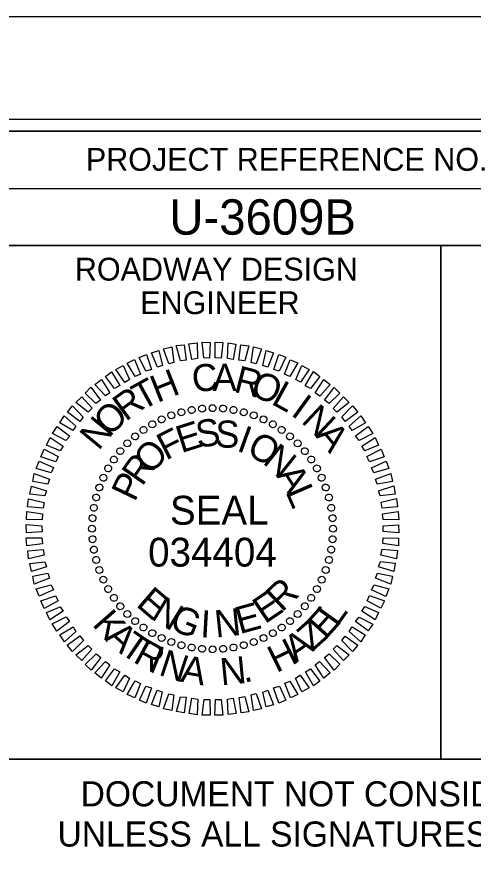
# Model space of a CAD drawing. Extents: x 2331575 to 2333259, y 609001 to 610101.
# Drawn here: x 2333049.3 to 2333149.3, y 609916 to 610101.5 of the extents above; entities that cross this region are included whole.
import ezdxf

# ---------------------------------------------------------------- set-up
doc = ezdxf.new("R2010")
doc.units = 0
for name, color, linetype in [('Sheet Cutting Line CELL', 7, 'Continuous'), ('Sheet Data Field CELL', 7, 'Continuous'), ('Sheet Plan CELL', 7, 'Continuous'), ('Sheet Plot Border Inside CELL', 7, 'Continuous'), ('Sheet Plot Border Outside CELL', 7, 'Continuous'), ('Sheet Profile CELL', 7, 'Continuous'), ('Sheet Profile Grid Major CELL', 7, 'Continuous'), ('Sheet Sticker Exception Certification CELL', 7, 'Continuous')]:
    doc.layers.add(name, color=color, linetype=linetype)

msp = doc.modelspace()

# ---------------------------------------------------------------- linework, layer by layer
at = {"layer": 'Sheet Cutting Line CELL'}
msp.add_line((2333259.23, 610101.48), (2331575.23, 610101.48), dxfattribs=at)
at = {"layer": 'Sheet Data Field CELL'}
for p, q in [((2333089.86, 610015.73), (2333089.86, 610015.73)), ((2333092.18, 610015.83), (2333092.18, 610015.83)), ((2333094.49, 610015.71), (2333094.49, 610015.71)), ((2333083.09, 610014.25), (2333083.09, 610014.25)), ((2333085.29, 610014.92), (2333085.29, 610014.92)), ((2333087.6, 610015.38), (2333087.6, 610015.38)), ((2333096.77, 610015.38), (2333096.77, 610015.38)), ((2333098.99, 610014.95), (2333098.99, 610014.95)), ((2333101.21, 610014.25), (2333101.21, 610014.25)), ((2333078.97, 610012.28), (2333078.97, 610012.28)), ((2333081, 610013.37), (2333081, 610013.37)), ((2333103.33, 610013.34), (2333103.33, 610013.34)), ((2333105.4, 610012.32), (2333105.4, 610012.32)), ((2333076.99, 610011.03), (2333076.99, 610011.03)), ((2333107.32, 610011.04), (2333107.32, 610011.04)), ((2333073.46, 610008.07), (2333073.46, 610008.07)), ((2333075.17, 610009.69), (2333075.17, 610009.69)), ((2333109.19, 610009.65), (2333109.19, 610009.65)), ((2333110.85, 610008.1), (2333110.85, 610008.1)), ((2333071.91, 610006.42), (2333071.91, 610006.42)), ((2333112.46, 610006.39), (2333112.46, 610006.39)), ((2333070.52, 610004.55), (2333070.52, 610004.55)), ((2333113.81, 610004.57), (2333113.81, 610004.57)), ((2333069.23, 610002.63), (2333069.23, 610002.63)), ((2333115.05, 610002.59), (2333115.05, 610002.59)), ((2333068.22, 610000.56), (2333068.22, 610000.56)), ((2333116.14, 610000.55), (2333116.14, 610000.55)), ((2333067.3, 609998.43), (2333067.3, 609998.43)), ((2333117.02, 609998.46), (2333117.02, 609998.46)), ((2333066.61, 609996.21), (2333066.61, 609996.21)), ((2333117.69, 609996.26), (2333117.69, 609996.26)), ((2333066.17, 609993.99), (2333066.17, 609993.99)), ((2333118.15, 609993.95), (2333118.15, 609993.95)), ((2333065.84, 609991.72), (2333065.84, 609991.72)), ((2333118.51, 609991.69), (2333118.51, 609991.69)), ((2333065.72, 609989.4), (2333065.72, 609989.4)), ((2333118.6, 609989.38), (2333118.6, 609989.38)), ((2333065.82, 609987.09), (2333065.82, 609987.09)), ((2333118.49, 609987.06), (2333118.49, 609987.06)), ((2333066.17, 609984.83), (2333066.17, 609984.83)), ((2333118.16, 609984.79), (2333118.16, 609984.79)), ((2333066.63, 609982.52), (2333066.63, 609982.52)), ((2333117.72, 609982.57), (2333117.72, 609982.57)), ((2333067.3, 609980.32), (2333067.3, 609980.32)), ((2333117.02, 609980.34), (2333117.02, 609980.34)), ((2333068.18, 609978.23), (2333068.18, 609978.23)), ((2333116.11, 609978.22), (2333116.11, 609978.22)), ((2333069.27, 609976.19), (2333069.27, 609976.19)), ((2333115.09, 609976.15), (2333115.09, 609976.15)), ((2333070.52, 609974.21), (2333070.52, 609974.21)), ((2333113.81, 609974.23), (2333113.81, 609974.23)), ((2333071.87, 609972.39), (2333071.87, 609972.39)), ((2333112.42, 609972.36), (2333112.42, 609972.36)), ((2333073.48, 609970.68), (2333073.48, 609970.68)), ((2333075.14, 609969.13), (2333075.14, 609969.13)), ((2333110.87, 609970.7), (2333110.87, 609970.7)), ((2333077, 609967.74), (2333077, 609967.74)), ((2333107.34, 609967.74), (2333107.34, 609967.74)), ((2333109.16, 609969.09), (2333109.16, 609969.09)), ((2333078.92, 609966.46), (2333078.92, 609966.46)), ((2333080.99, 609965.44), (2333080.99, 609965.44)), ((2333103.33, 609965.41), (2333103.33, 609965.41)), ((2333105.36, 609966.5), (2333105.36, 609966.5)), ((2333083.12, 609964.53), (2333083.12, 609964.53)), ((2333085.34, 609963.83), (2333085.34, 609963.83)), ((2333099.03, 609963.86), (2333099.03, 609963.86)), ((2333101.23, 609964.53), (2333101.23, 609964.53)), ((2333087.56, 609963.4), (2333087.56, 609963.4)), ((2333089.83, 609963.07), (2333089.83, 609963.07)), ((2333092.15, 609962.95), (2333092.15, 609962.95)), ((2333094.47, 609963.04), (2333094.47, 609963.04)), ((2333096.73, 609963.4), (2333096.73, 609963.4))]:
    msp.add_line(p, q, dxfattribs=at)
for points in [[(2333082.58, 610025.51), (2333081.42, 610028.81), (2333083.2, 610029.21), (2333083.68, 610025.79)], [(2333085.1, 610026.13), (2333084.19, 610029.49), (2333085.93, 610029.68), (2333086.36, 610026.31)], [(2333087.62, 610026.49), (2333086.98, 610029.85), (2333088.77, 610030.09), (2333088.88, 610026.67)], [(2333090.25, 610026.8), (2333089.92, 610030.22), (2333091.66, 610030.2), (2333091.51, 610026.77)], [(2333092.77, 610026.79), (2333092.71, 610030.22), (2333094.45, 610030.19), (2333094.04, 610026.76)], [(2333095.41, 610026.68), (2333095.56, 610030.11), (2333097.3, 610029.82), (2333096.68, 610026.49)], [(2333097.94, 610026.3), (2333098.36, 610029.68), (2333100.1, 610029.45), (2333099.21, 610026.17)], [(2333100.64, 610025.77), (2333101.11, 610029.2), (2333102.9, 610028.81), (2333101.75, 610025.53)], [(2333077.5, 610023.89), (2333076.08, 610026.92), (2333077.65, 610027.58), (2333078.81, 610024.23)], [(2333080.06, 610024.78), (2333078.8, 610027.92), (2333080.42, 610028.42), (2333081.16, 610025.17)], [(2333103.18, 610025.13), (2333103.91, 610028.41), (2333105.55, 610027.91), (2333104.29, 610024.78)], [(2333105.56, 610024.23), (2333106.72, 610027.56), (2333108.2, 610026.96), (2333106.78, 610023.88)], [(2333072.96, 610021.44), (2333070.96, 610024.25), (2333072.58, 610025.12), (2333073.95, 610022.09)], [(2333075.2, 610022.75), (2333073.46, 610025.67), (2333075.08, 610026.43), (2333076.35, 610023.24)], [(2333107.95, 610023.27), (2333109.21, 610026.4), (2333110.86, 610025.69), (2333109.12, 610022.71)], [(2333110.39, 610022.1), (2333111.76, 610025.12), (2333113.36, 610024.26), (2333111.41, 610021.48)], [(2333070.67, 610020.09), (2333068.67, 610022.74), (2333070.02, 610023.76), (2333071.81, 610020.74)], [(2333112.47, 610020.71), (2333114.26, 610023.8), (2333115.65, 610022.72), (2333113.64, 610020.1)], [(2333068.69, 610018.47), (2333066.38, 610020.96), (2333067.79, 610022.09), (2333069.68, 610019.17)], [(2333114.66, 610019.17), (2333116.56, 610022.1), (2333117.95, 610020.97), (2333115.67, 610018.45)], [(2333066.61, 610016.8), (2333064.26, 610019.08), (2333065.5, 610020.37), (2333067.6, 610017.56)], [(2333116.69, 610017.57), (2333118.8, 610020.35), (2333120.08, 610019.11), (2333117.7, 610016.8)], [(2333064.91, 610014.93), (2333062.19, 610017.04), (2333063.48, 610018.28), (2333065.74, 610015.79)], [(2333118.62, 610015.76), (2333120.84, 610018.28), (2333122.12, 610017.04), (2333119.42, 610014.93)], [(2333063.1, 610012.9), (2333060.33, 610014.9), (2333061.46, 610016.29), (2333063.82, 610013.86)], [(2333120.49, 610013.9), (2333122.87, 610016.31), (2333124, 610014.91), (2333121.25, 610012.86)], [(2333061.56, 610010.87), (2333058.68, 610012.61), (2333059.66, 610014.15), (2333062.22, 610011.88)], [(2333122.11, 610011.87), (2333124.65, 610014.13), (2333125.68, 610012.62), (2333122.76, 610010.88)], [(2333123.51, 610009.74), (2333126.27, 610011.79), (2333127.3, 610010.23), (2333124.27, 610008.7)], [(2333060.01, 610008.74), (2333057.04, 610010.26), (2333058.07, 610011.76), (2333060.84, 610009.7)], [(2333058.79, 610006.45), (2333055.77, 610007.71), (2333056.53, 610009.36), (2333059.4, 610007.46)], [(2333124.92, 610007.45), (2333127.84, 610009.34), (2333128.55, 610007.72), (2333125.57, 610006.46)], [(2333057.78, 610004.01), (2333054.49, 610005.16), (2333055.26, 610006.81), (2333058.29, 610005.18)], [(2333126.01, 610005.2), (2333129.09, 610006.83), (2333129.81, 610005.16), (2333126.56, 610004.05)], [(2333056.77, 610001.67), (2333053.49, 610002.56), (2333054.14, 610004.21), (2333057.33, 610002.79)], [(2333127.01, 610002.74), (2333130.19, 610004.17), (2333130.8, 610002.55), (2333127.55, 610001.65)], [(2333056.02, 609999.13), (2333052.74, 609999.76), (2333053.08, 610001.5), (2333056.42, 610000.25)], [(2333127.89, 610000.23), (2333131.24, 610001.5), (2333131.59, 609999.77), (2333128.28, 609999.13)], [(2333055.38, 609996.59), (2333052.11, 609996.96), (2333052.45, 609998.75), (2333055.78, 609997.71)], [(2333128.57, 609997.71), (2333131.87, 609998.77), (2333132.22, 609996.99), (2333128.9, 609996.61)], [(2333055.01, 609993.9), (2333051.63, 609994.16), (2333051.81, 609995.95), (2333055.25, 609995.17)], [(2333129.09, 609995.2), (2333132.5, 609995.99), (2333132.69, 609994.2), (2333129.32, 609993.93)], [(2333054.79, 609991.37), (2333051.36, 609991.41), (2333051.44, 609993.15), (2333054.87, 609992.63)], [(2333129.45, 609992.67), (2333132.86, 609993.15), (2333133, 609991.37), (2333129.57, 609991.41)], [(2333054.78, 609988.74), (2333051.36, 609988.52), (2333051.33, 609990.31), (2333054.76, 609990)], [(2333129.55, 609990.04), (2333132.96, 609990.26), (2333133, 609988.47), (2333129.57, 609988.78)], [(2333054.88, 609986.1), (2333051.46, 609985.62), (2333051.33, 609987.41), (2333054.75, 609987.37)], [(2333129.54, 609987.41), (2333132.96, 609987.36), (2333132.89, 609985.62), (2333129.46, 609986.14)], [(2333055.24, 609983.58), (2333051.83, 609982.79), (2333051.64, 609984.57), (2333055.01, 609984.84)], [(2333129.32, 609984.88), (2333132.7, 609984.62), (2333132.52, 609982.83), (2333129.08, 609983.61)], [(2333055.76, 609981.06), (2333052.46, 609980.01), (2333052.11, 609981.79), (2333055.42, 609982.16)], [(2333128.95, 609982.18), (2333132.22, 609981.82), (2333131.88, 609980.02), (2333128.54, 609981.07)], [(2333056.43, 609978.55), (2333053.09, 609977.28), (2333052.74, 609979.01), (2333056.05, 609979.65)], [(2333128.31, 609979.64), (2333131.58, 609979.02), (2333131.24, 609977.27), (2333127.9, 609978.53)], [(2333057.32, 609976.03), (2333054.13, 609974.61), (2333053.52, 609976.23), (2333056.77, 609977.13)], [(2333127.56, 609977.1), (2333130.84, 609976.21), (2333130.18, 609974.57), (2333127, 609975.99)], [(2333058.31, 609973.58), (2333055.23, 609971.94), (2333054.52, 609973.62), (2333057.76, 609974.73)], [(2333126.55, 609974.77), (2333129.83, 609973.61), (2333129.07, 609971.97), (2333126.04, 609973.6)], [(2333059.4, 609971.33), (2333056.49, 609969.44), (2333055.77, 609971.06), (2333058.75, 609972.32)], [(2333125.54, 609972.33), (2333128.56, 609971.06), (2333127.8, 609969.42), (2333124.92, 609971.32)], [(2333060.81, 609969.04), (2333058.06, 609966.99), (2333057.03, 609968.55), (2333060.06, 609970.08)], [(2333124.31, 609970.04), (2333127.29, 609968.51), (2333126.26, 609967.02), (2333123.49, 609969.08)], [(2333062.22, 609966.9), (2333059.68, 609964.65), (2333058.65, 609966.16), (2333061.57, 609967.89)], [(2333122.77, 609967.91), (2333125.64, 609966.17), (2333124.67, 609964.62), (2333122.1, 609966.9)], [(2333063.84, 609964.88), (2333061.45, 609962.47), (2333060.32, 609963.87), (2333063.08, 609965.92)], [(2333121.22, 609965.88), (2333124, 609963.87), (2333122.86, 609962.49), (2333120.5, 609964.92)], [(2333065.71, 609963.01), (2333063.49, 609960.5), (2333062.2, 609961.74), (2333064.91, 609963.84)], [(2333119.42, 609963.85), (2333122.14, 609961.74), (2333120.84, 609960.5), (2333118.59, 609962.99)], [(2333067.64, 609961.2), (2333065.53, 609958.43), (2333064.24, 609959.67), (2333066.62, 609961.98)], [(2333117.71, 609961.97), (2333120.07, 609959.7), (2333118.83, 609958.41), (2333116.72, 609961.22)], [(2333069.67, 609959.61), (2333067.77, 609956.68), (2333066.38, 609957.81), (2333068.66, 609960.33)], [(2333115.63, 609960.31), (2333117.94, 609957.82), (2333116.54, 609956.69), (2333114.65, 609959.6)], [(2333071.85, 609958.07), (2333070.06, 609954.98), (2333068.68, 609956.06), (2333070.68, 609958.68)], [(2333113.66, 609958.69), (2333115.66, 609956.04), (2333114.3, 609955.02), (2333112.51, 609958.04)], [(2333073.93, 609956.68), (2333072.56, 609953.65), (2333070.97, 609954.52), (2333072.92, 609957.29)], [(2333111.37, 609957.33), (2333113.37, 609954.52), (2333111.75, 609953.65), (2333110.38, 609956.68)], [(2333076.38, 609955.51), (2333075.11, 609952.38), (2333073.47, 609953.09), (2333075.21, 609956.07)], [(2333078.76, 609954.55), (2333077.61, 609951.21), (2333076.12, 609951.82), (2333077.54, 609954.9)], [(2333106.83, 609954.88), (2333108.25, 609951.85), (2333106.68, 609951.2), (2333105.52, 609954.55)], [(2333109.13, 609956.03), (2333110.86, 609953.11), (2333109.24, 609952.35), (2333107.98, 609955.54)], [(2333081.15, 609953.65), (2333080.42, 609950.37), (2333078.77, 609950.87), (2333080.04, 609954)], [(2333083.69, 609953.01), (2333083.22, 609949.57), (2333081.42, 609949.96), (2333082.58, 609953.25)], [(2333086.38, 609952.47), (2333085.97, 609949.1), (2333084.23, 609949.33), (2333085.12, 609952.61)], [(2333099.23, 609952.65), (2333100.13, 609949.29), (2333098.4, 609949.1), (2333097.97, 609952.46)], [(2333101.75, 609953.27), (2333102.91, 609949.97), (2333101.13, 609949.57), (2333100.65, 609952.99)], [(2333104.26, 609954), (2333105.53, 609950.86), (2333103.91, 609950.36), (2333103.16, 609953.61)], [(2333088.92, 609952.1), (2333088.77, 609948.67), (2333087.02, 609948.96), (2333087.65, 609952.29)], [(2333091.55, 609951.98), (2333091.61, 609948.56), (2333089.87, 609948.58), (2333090.29, 609952.01)], [(2333094.08, 609951.98), (2333094.4, 609948.56), (2333092.67, 609948.58), (2333092.82, 609952.01)], [(2333096.71, 609952.29), (2333097.35, 609948.93), (2333095.56, 609948.68), (2333095.45, 609952.1)]]:
    msp.add_lwpolyline(points, close=True, dxfattribs=at)
for centre, major_axis in [((2333085.33, 610014.9), (-0.196, 0.732)), ((2333087.58, 610015.4), (-0.132, 0.747)), ((2333089.86, 610015.7), (-0.066, 0.755)), ((2333092.16, 610015.8), (0, 0.758)), ((2333094.47, 610015.7), (0.066, 0.755)), ((2333096.75, 610015.4), (0.132, 0.747)), ((2333099, 610014.9), (0.196, 0.732)), ((2333081, 610013.33), (-0.32, 0.687)), ((2333083.13, 610014.21), (-0.259, 0.713)), ((2333101.2, 610014.21), (0.259, 0.713)), ((2333103.33, 610013.33), (0.32, 0.687)), ((2333077.01, 610011.03), (-0.435, 0.621)), ((2333078.96, 610012.26), (-0.379, 0.657)), ((2333105.37, 610012.26), (0.379, 0.657)), ((2333107.31, 610011.03), (0.435, 0.621)), ((2333075.18, 610009.62), (-0.487, 0.581)), ((2333109.14, 610009.62), (0.487, 0.581)), ((2333073.49, 610008.07), (-0.536, 0.536)), ((2333110.84, 610008.07), (0.536, 0.536)), ((2333071.93, 610006.37), (-0.581, 0.487)), ((2333112.4, 610006.37), (0.581, 0.487)), ((2333070.53, 610004.54), (-0.621, 0.435)), ((2333113.8, 610004.54), (0.621, 0.435)), ((2333069.29, 610002.6), (-0.657, 0.379)), ((2333115.04, 610002.6), (0.657, 0.379)), ((2333068.22, 610000.55), (-0.687, 0.32)), ((2333116.1, 610000.55), (0.687, 0.32)), ((2333067.34, 609998.42), (-0.713, 0.259)), ((2333116.98, 609998.42), (0.713, 0.259)), ((2333066.65, 609996.22), (-0.732, 0.196)), ((2333117.68, 609996.23), (0.732, 0.196)), ((2333066.15, 609993.98), (-0.747, 0.132)), ((2333118.18, 609993.98), (0.747, 0.132)), ((2333065.85, 609991.69), (-0.755, 0.066)), ((2333118.48, 609991.69), (0.755, 0.066)), ((2333065.75, 609989.39), (-0.758, 0)), ((2333118.58, 609989.39), (0.758, 0)), ((2333065.85, 609987.09), (-0.755, -0.066)), ((2333118.48, 609987.09), (0.755, -0.066)), ((2333066.15, 609984.8), (-0.747, -0.132)), ((2333118.18, 609984.8), (0.747, -0.132)), ((2333066.65, 609982.55), (-0.732, -0.196)), ((2333117.68, 609982.55), (0.732, -0.196)), ((2333067.34, 609980.35), (-0.713, -0.259)), ((2333116.98, 609980.35), (0.713, -0.259)), ((2333068.22, 609978.23), (-0.687, -0.32)), ((2333116.1, 609978.23), (0.687, -0.32)), ((2333069.29, 609976.18), (-0.657, -0.379)), ((2333115.04, 609976.18), (0.657, -0.379)), ((2333070.53, 609974.24), (-0.621, -0.435)), ((2333113.8, 609974.24), (0.621, -0.435)), ((2333071.93, 609972.41), (-0.581, -0.487)), ((2333112.4, 609972.41), (0.581, -0.487)), ((2333073.49, 609970.71), (-0.536, -0.536)), ((2333110.84, 609970.71), (0.536, -0.536)), ((2333075.19, 609969.15), (-0.487, -0.581)), ((2333109.14, 609969.15), (0.487, -0.581)), ((2333077.01, 609967.75), (-0.435, -0.621)), ((2333078.96, 609966.51), (-0.379, -0.657)), ((2333105.37, 609966.51), (0.379, -0.657)), ((2333107.31, 609967.75), (0.435, -0.621)), ((2333081, 609965.45), (-0.32, -0.687)), ((2333083.13, 609964.57), (-0.259, -0.713)), ((2333101.2, 609964.57), (0.259, -0.713)), ((2333103.33, 609965.45), (0.32, -0.687)), ((2333085.33, 609963.87), (-0.196, -0.732)), ((2333087.58, 609963.38), (-0.132, -0.747)), ((2333089.86, 609963.08), (-0.066, -0.755)), ((2333092.16, 609962.97), (0, -0.758)), ((2333094.47, 609963.08), (0.066, -0.755)), ((2333096.75, 609963.38), (0.132, -0.747)), ((2333099, 609963.88), (0.196, -0.732))]:
    msp.add_ellipse(centre, major_axis=major_axis, ratio=0.999708, dxfattribs=at)
at = {"layer": 'Sheet Plot Border Inside CELL'}
msp.add_lwpolyline([(2331588.23, 609023.93), (2333254.73, 609023.93), (2333254.73, 610079.03), (2331588.23, 610079.03)], close=True, dxfattribs=at)
at = {"layer": 'Sheet Plot Border Outside CELL'}
msp.add_lwpolyline([(2331575.23, 609001.48), (2333259.23, 609001.48), (2333259.23, 610101.48), (2331575.23, 610101.48)], close=True, dxfattribs=at)
at = {"layer": 'Sheet Profile CELL'}
for p, q in [((2333042.18, 610063.93), (2333242.23, 610063.93)), ((2333142.23, 610051.43), (2333142.23, 609938.98))]:
    msp.add_line(p, q, dxfattribs=at)
for points in [[(2333242.23, 610076.48), (2331742.23, 610076.48), (2331742.23, 609026.48), (2333242.23, 609026.48)], [(2333042.18, 610076.48), (2333242.23, 610076.48), (2333242.23, 610051.43), (2333042.18, 610051.43)], [(2333042.18, 610051.43), (2333142.23, 610051.43), (2333142.23, 609938.93), (2333042.18, 609938.93)], [(2333142.23, 610051.43), (2333242.23, 610051.43), (2333242.23, 609938.93), (2333142.23, 609938.93)]]:
    msp.add_lwpolyline(points, close=True, dxfattribs=at)
at = {"layer": 'Sheet Profile Grid Major CELL'}
msp.add_lwpolyline([(2332742.23, 610076.48), (2332792.23, 610076.48), (2332792.23, 609576.48), (2332842.23, 609576.48), (2332842.23, 610076.48), (2332892.23, 610076.48), (2332892.23, 609576.48), (2332942.23, 609576.48), (2332942.23, 610076.48), (2332992.23, 610076.48), (2332992.23, 609576.48), (2333042.23, 609576.48), (2333042.23, 610076.48), (2333068.53, 610076.48)], dxfattribs=at)
at = {"layer": 'Sheet Sticker Exception Certification CELL'}
msp.add_line((2333042.18, 609938.93), (2333242.21, 609938.93), dxfattribs=at)
msp.add_line((2333042.18, 609938.93), (2333242.21, 609938.93), dxfattribs=at)

# ---------------------------------------------------------------- texts
at = {"layer": 'Sheet Data Field CELL'}
msp.add_text('U-3609B', height=7.75, dxfattribs=at).set_placement((2333082.69, 610053.79))
for s, height, rotation, p in [('C', 5.94, 7.2205, (2333088.01, 610019.18)), ('A', 5.94, 0.021, (2333092.16, 610019.57)), ('R', 5.94, 345.6217, (2333096.59, 610019.43)), ('H', 5.94, 21.6201, (2333080.04, 610016.93)), ('O', 5.94, 338.4218, (2333100.13, 610018.71)), ('T', 5.94, 28.8204, (2333076.65, 610015.14)), ('L', 5.94, 331.2215, (2333104.8, 610016.84)), ('R', 5.94, 36.0212, (2333073.11, 610012.76)), ('I', 5.94, 324.0208, (2333109.11, 610014.39)), ('O', 5.94, 43.2224, (2333069.54, 610009.43)), ('N', 5.94, 316.8196, (2333111.4, 610012.79)), ('N', 5.94, 50.4241, (2333067.17, 610006.33)), ('E', 5.94, 17.6117, (2333085.29, 610005.91)), ('S', 5.94, 8.2563, (2333088.91, 610007.08)), ('S', 5.94, 358.901, (2333092.7, 610007.2)), ('I', 5.94, 340.1903, (2333097.24, 610006.54)), ('A', 5.94, 309.6178, (2333114.56, 610009.74)), ('F', 5.94, 26.9677, (2333081.95, 610004.27)), ('O', 5.94, 330.8341, (2333099.35, 610005.84)), ('O', 5.94, 45.6819, (2333078.53, 610001.11)), ('N', 5.94, 321.4773, (2333102.92, 610003.8)), ('R', 5.94, 55.0403, (2333076.73, 609998.49)), ('P', 5.94, 64.3995, (2333075.1, 609995.09)), ('A', 5.94, 302.7609, (2333105.97, 610001.11)), ('L', 5.94, 293.4015, (2333108.08, 609997.51)), ('SEAL', 6.317, 0.0006, (2333082.83, 609990.28)), ('034404', 6.319, 0.0006, (2333078.04, 609981.1)), ('E', 5.94, 319.2775, (2333075.18, 609972.61)), ('R', 5.94, 43.4821, (2333107.34, 609970.96)), ('E', 5.94, 34.1247, (2333103.64, 609968.42)), ('N', 5.94, 328.6346, (2333078.39, 609969.82)), ('E', 5.94, 15.4124, (2333098.1, 609966.27)), ('K', 5.94, 311.1686, (2333065.62, 609968.37)), ('G', 5.94, 337.9909, (2333082.43, 609967.52)), ('I', 5.94, 356.7018, (2333089.37, 609965.64)), ('N', 5.94, 6.057, (2333092.9, 609965.54)), ('E', 5.94, 48.1249, (2333116.94, 609964.96)), ('L', 5.94, 54.2997, (2333119.43, 609967.7)), ('Z', 5.94, 41.5854, (2333114, 609962.37)), ('A', 5.94, 318.0728, (2333068.34, 609965.26)), ('T', 5.94, 325.3226, (2333071.58, 609962.36)), ('A', 5.94, 34.3357, (2333110.42, 609959.91)), ('R', 5.94, 331.3054, (2333074.52, 609960.3)), ('I', 5.94, 337.7105, (2333077.87, 609958.44)), ('H', 5.94, 26.3758, (2333106.17, 609957.75)), ('N', 5.94, 341.8314, (2333080.14, 609957.45)), ('A', 5.94, 350.252, (2333084.95, 609955.94)), ('N', 5.94, 5.596, (2333094.08, 609955.06)), ('.', 5.94, 14.0166, (2333099.09, 609955.62))]:
    msp.add_text(s, height=height, rotation=rotation, dxfattribs=at).set_placement(p)
at = {"layer": 'Sheet Plan CELL'}
msp.add_text('ENGINEER', height=5, rotation=0, dxfattribs=at).set_placement((2333076.31, 610036.39))
at = {"layer": 'Sheet Profile CELL'}
for s, p in [('PROJECT REFERENCE NO.', (2333064.39, 610067.79)), ('ROADWAY DESIGN', (2333061.98, 610043.74))]:
    msp.add_text(s, height=5.0001, dxfattribs=at).set_placement(p)
at = {"layer": 'Sheet Sticker Exception Certification CELL'}
for s, p in [('DOCUMENT NOT CONSIDERED FINAL', (2333063.25, 609928.58)), ('DOCUMENT NOT CONSIDERED FINAL', (2333063.25, 609928.58)), ('UNLESS ALL SIGNATURES COMPLETED', (2333058.18, 609919.78)), ('UNLESS ALL SIGNATURES COMPLETED', (2333058.18, 609919.78))]:
    msp.add_text(s, height=5.5, dxfattribs=at).set_placement(p)

doc.saveas('drawing.dxf')
